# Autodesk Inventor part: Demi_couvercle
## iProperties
Created: 2011-01
Part Number: Demi_couvercle
Document SubType Name: Modeling
Designer: eric
Density: 1 g/cm^3
Mass: 66.4796 g
Surface Area: 900.231 cm^2
Volume: 66.4796 cm^3
Author: eric
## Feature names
1. Base1
